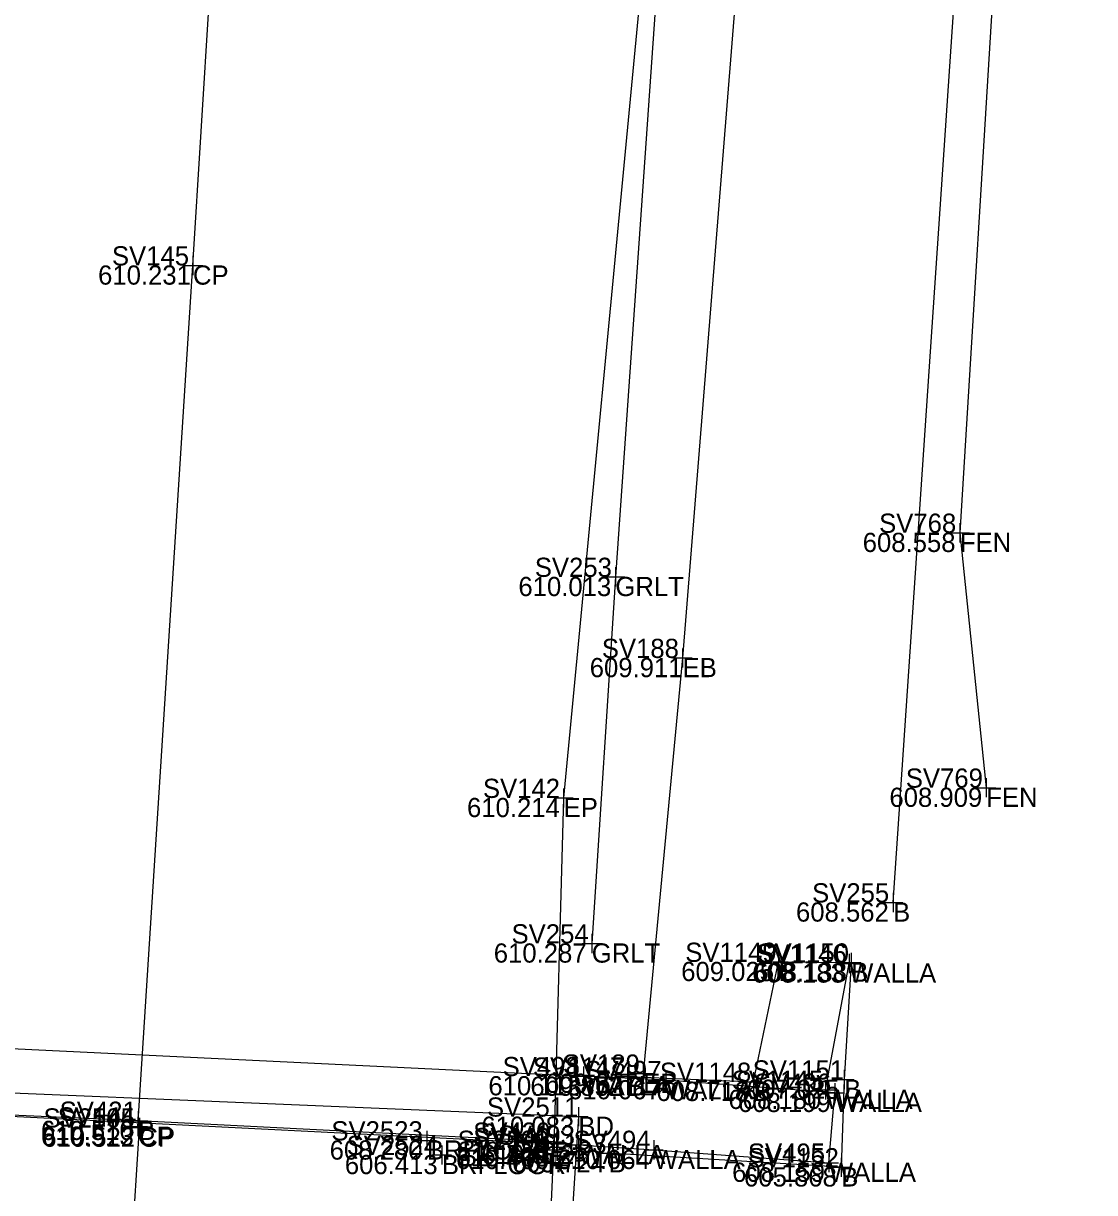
# Model space of a CAD drawing. Extents: x -2 to 1979875, y -2 to 232027.
# Drawn here: x 1978773.9 to 1978801.79, y 231291.3 to 231321.76 of the extents above; entities that cross this region are included whole.
import ezdxf

# ---------------------------------------------------------------- set-up
doc = ezdxf.new("R2010")
doc.units = 0
for name, color, linetype in [('_CIVIL_CONSTRUCTION', 7, 'Continuous'), ('BR_X_SV_Abut', 7, 'Continuous'), ('BR_X_SV_Deck_Floor_Text', 7, 'Continuous'), ('BR_X_SV_Deck_Top', 7, 'Continuous'), ('BR_X_SV_Deck_Top_Text', 7, 'Continuous'), ('GE_P_Alignment', 7, 'Continuous'), ('GE_P_Alignment_100_Curve_Data', 7, 'Continuous'), ('GE_P_Alignment_500_Stations', 7, 'Continuous'), ('GE_X_Alignment', 7, 'Continuous'), ('GE_X_Alignment_1000_Curve_Data', 7, 'Continuous'), ('GE_X_Alignment_1000_Stations', 7, 'Continuous'), ('GE_X_Alignment_100_Curve_Data', 7, 'Continuous'), ('GE_X_Alignment_100_Stations', 7, 'Continuous'), ('RD_X_Fence', 7, 'Continuous'), ('SC_Scratch1', 7, 'Continuous')]:
    doc.layers.add(name, color=color, linetype=linetype)

msp = doc.modelspace()

# ---------------------------------------------------------------- linework, layer by layer
at = {"layer": 'BR_X_SV_Abut'}
for p, q in [((1978764.58, 231295.485), (1978788.479, 231294.331)), ((1978764.125, 231293.766), (1978788.351, 231292.541))]:
    msp.add_line(p, q, dxfattribs=at)
for points in [[(1978794.786, 231293.976), (1978795.398, 231297.268)], [(1978788.351, 231292.541), (1978790.31, 231292.41), (1978794.873, 231292.077), (1978795.027, 231293.897), (1978790.63, 231294.228), (1978788.479, 231294.331)]]:
    msp.add_lwpolyline(points, dxfattribs=at)
at = {"layer": 'BR_X_SV_Deck_Top'}
msp.add_lwpolyline([(1978761.339, 231252.043), (1978764.257, 231294.289), (1978788.348, 231293.277), (1978785.624, 231251.227)], close=True, dxfattribs=at)
at = {"layer": 'GE_P_Alignment'}
for points in [[(1978796.543, 231298.857), (1978798.274, 231324.443), (1978800.704, 231350.055), (1978802.691, 231376.873), (1978804.911, 231401.653), (1978806.885, 231425.398), (1978807.692, 231450.453), (1978809.926, 231474.524), (1978811.781, 231491.704), (1978814.624, 231521.225), (1978818.445, 231546.214), (1978822.849, 231572.066), (1978827.059, 231594.68), (1978834.582, 231618.811), (1978841.486, 231643.192), (1978848.448, 231666.52), (1978859.661, 231691.186), (1978869.566, 231712.589), (1978880.404, 231735.407), (1978890.398, 231756.483), (1978895.241, 231765.92)], [(1978789.627, 231294.318), (1978792.909, 231294.183), (1978793.561, 231297.308), (1978795.454, 231297.29), (1978795.267, 231294.242), (1978795.191, 231291.956), (1978789.137, 231292.325)], [(1978787.716, 231292.624), (1978776.886, 231293.168), (1978764.446, 231293.727)]]:
    msp.add_lwpolyline(points, dxfattribs=at)
at = {"layer": 'GE_P_Alignment_100_Curve_Data'}
msp.add_lwpolyline([(1978801.365, 231447.686), (1978797.734, 231425.84), (1978795.609, 231402.949), (1978794.056, 231378.448), (1978792.74, 231353.579), (1978790.842, 231329.19), (1978789.312, 231307.337), (1978788.697, 231297.789)], dxfattribs=at)
at = {"layer": 'GE_X_Alignment_1000_Curve_Data'}
for points in [[(1978776.88, 231293.019), (1978778.313, 231315.451), (1978779.686, 231337.763), (1978781.119, 231360.475), (1978782.569, 231384.073), (1978784.079, 231408.548), (1978785.737, 231433.04), (1978787.352, 231456.369), (1978789.204, 231480.117), (1978791.477, 231503.648), (1978794.349, 231526.784), (1978797.796, 231550.891), (1978801.515, 231572.898), (1978806.442, 231596.208), (1978812.098, 231619.057), (1978818.629, 231640.775), (1978826, 231662.112), (1978835.057, 231685.412), (1978844.843, 231707.874), (1978854.489, 231728.841), (1978864.575, 231749.812), (1978877.222, 231774.568)], [(1978774.433, 231252.669), (1978775.92, 231277.185), (1978776.918, 231292.992)]]:
    msp.add_lwpolyline(points, dxfattribs=at)
at = {"layer": 'GE_X_Alignment_1000_Stations'}
for points in [[(1978887.054, 231769.497), (1978875.688, 231747.111), (1978865.322, 231725.635), (1978856.257, 231705.079), (1978847.493, 231684.376), (1978839.463, 231663.377), (1978831.793, 231640.155), (1978824.647, 231616.117), (1978817.773, 231591.521), (1978812.873, 231567.295), (1978809.011, 231544.227), (1978805.416, 231519.882), (1978802.367, 231496.191), (1978799.68, 231465.625), (1978797.956, 231442.353), (1978795.891, 231416.691), (1978793.937, 231391.428), (1978792.627, 231370.424), (1978791.336, 231345.811), (1978789.97, 231322.684), (1978787.965, 231301.579), (1978787.711, 231292.48)], [(1978787.697, 231292.411), (1978786.77, 231271.728), (1978785.515, 231252.063)]]:
    msp.add_lwpolyline(points, dxfattribs=at)
at = {"layer": 'GE_X_Alignment_100_Curve_Data'}
for p, q in [((1978778.313, 231315.701), (1978778.313, 231315.201)), ((1978778.063, 231315.451), (1978778.563, 231315.451)), ((1978778.313, 231315.451), (1978778.313, 231315.451)), ((1978798.282, 231308.736), (1978798.282, 231308.236)), ((1978798.032, 231308.486), (1978798.532, 231308.486)), ((1978798.282, 231308.486), (1978798.282, 231308.486)), ((1978789.062, 231307.337), (1978789.562, 231307.337)), ((1978789.312, 231307.587), (1978789.312, 231307.087)), ((1978789.312, 231307.337), (1978789.312, 231307.337)), ((1978790.812, 231305.225), (1978791.312, 231305.225)), ((1978791.062, 231305.475), (1978791.062, 231304.975)), ((1978791.062, 231305.225), (1978791.062, 231305.225)), ((1978787.965, 231301.829), (1978787.965, 231301.329)), ((1978798.718, 231301.846), (1978799.218, 231301.846)), ((1978798.968, 231302.096), (1978798.968, 231301.596)), ((1978798.968, 231301.846), (1978798.968, 231301.846)), ((1978787.715, 231301.579), (1978788.215, 231301.579)), ((1978787.965, 231301.579), (1978787.965, 231301.579)), ((1978796.543, 231299.107), (1978796.543, 231298.607)), ((1978796.293, 231298.857), (1978796.793, 231298.857)), ((1978796.543, 231298.857), (1978796.543, 231298.857)), ((1978788.697, 231298.039), (1978788.697, 231297.539)), ((1978788.447, 231297.789), (1978788.947, 231297.789)), ((1978788.697, 231297.789), (1978788.697, 231297.789)), ((1978793.311, 231297.308), (1978793.811, 231297.308)), ((1978793.561, 231297.558), (1978793.561, 231297.058)), ((1978793.561, 231297.308), (1978793.561, 231297.308)), ((1978795.148, 231297.268), (1978795.648, 231297.268)), ((1978795.204, 231297.29), (1978795.704, 231297.29)), ((1978795.398, 231297.518), (1978795.398, 231297.018)), ((1978795.398, 231297.268), (1978795.398, 231297.268)), ((1978795.454, 231297.54), (1978795.454, 231297.04)), ((1978795.454, 231297.29), (1978795.454, 231297.29)), ((1978788.479, 231294.581), (1978788.479, 231294.081)), ((1978789.627, 231294.568), (1978789.627, 231294.068)), ((1978790.036, 231294.646), (1978790.036, 231294.146)), ((1978788.229, 231294.331), (1978788.729, 231294.331)), ((1978788.479, 231294.331), (1978788.479, 231294.331)), ((1978789.377, 231294.318), (1978789.877, 231294.318)), ((1978789.627, 231294.318), (1978789.627, 231294.318)), ((1978789.786, 231294.396), (1978790.286, 231294.396)), ((1978790.036, 231294.396), (1978790.036, 231294.396)), ((1978790.38, 231294.228), (1978790.88, 231294.228)), ((1978790.63, 231294.478), (1978790.63, 231293.978)), ((1978790.63, 231294.228), (1978790.63, 231294.228)), ((1978792.909, 231294.433), (1978792.909, 231293.933)), ((1978794.786, 231294.226), (1978794.786, 231293.726)), ((1978795.017, 231294.242), (1978795.517, 231294.242)), ((1978795.267, 231294.492), (1978795.267, 231293.992)), ((1978795.267, 231294.242), (1978795.267, 231294.242)), ((1978792.659, 231294.183), (1978793.159, 231294.183)), ((1978792.909, 231294.183), (1978792.909, 231294.183)), ((1978794.536, 231293.976), (1978795.036, 231293.976)), ((1978794.786, 231293.976), (1978794.786, 231293.976)), ((1978795.027, 231294.147), (1978795.027, 231293.647)), ((1978794.777, 231293.897), (1978795.277, 231293.897)), ((1978795.027, 231293.897), (1978795.027, 231293.897)), ((1978776.886, 231293.418), (1978776.886, 231292.918)), ((1978788.348, 231293.527), (1978788.348, 231293.027)), ((1978776.63, 231293.019), (1978777.13, 231293.019)), ((1978776.636, 231293.168), (1978777.136, 231293.168)), ((1978776.88, 231293.269), (1978776.88, 231292.769)), ((1978776.88, 231293.019), (1978776.88, 231293.019)), ((1978776.886, 231293.168), (1978776.886, 231293.168)), ((1978776.918, 231293.242), (1978776.918, 231292.742)), ((1978788.098, 231293.277), (1978788.598, 231293.277)), ((1978788.348, 231293.277), (1978788.348, 231293.277)), ((1978776.668, 231292.992), (1978777.168, 231292.992)), ((1978776.918, 231292.992), (1978776.918, 231292.992)), ((1978784.403, 231292.907), (1978784.403, 231292.407)), ((1978787.711, 231292.73), (1978787.711, 231292.23)), ((1978787.716, 231292.874), (1978787.716, 231292.374)), ((1978788.351, 231292.791), (1978788.351, 231292.291)), ((1978784.153, 231292.657), (1978784.653, 231292.657)), ((1978784.403, 231292.657), (1978784.403, 231292.657)), ((1978784.793, 231292.528), (1978784.793, 231292.028)), ((1978787.447, 231292.411), (1978787.947, 231292.411)), ((1978787.461, 231292.48), (1978787.961, 231292.48)), ((1978787.466, 231292.624), (1978787.966, 231292.624)), ((1978787.697, 231292.661), (1978787.697, 231292.161)), ((1978787.697, 231292.411), (1978787.697, 231292.411)), ((1978787.711, 231292.48), (1978787.711, 231292.48)), ((1978787.716, 231292.624), (1978787.716, 231292.624)), ((1978788.101, 231292.541), (1978788.601, 231292.541)), ((1978788.351, 231292.541), (1978788.351, 231292.541)), ((1978789.137, 231292.575), (1978789.137, 231292.075)), ((1978790.06, 231292.41), (1978790.56, 231292.41)), ((1978790.31, 231292.66), (1978790.31, 231292.16)), ((1978790.31, 231292.41), (1978790.31, 231292.41)), ((1978784.543, 231292.278), (1978785.043, 231292.278)), ((1978784.793, 231292.278), (1978784.793, 231292.278)), ((1978788.887, 231292.325), (1978789.387, 231292.325)), ((1978789.137, 231292.325), (1978789.137, 231292.325)), ((1978794.873, 231292.327), (1978794.873, 231291.827)), ((1978795.191, 231292.206), (1978795.191, 231291.706)), ((1978794.623, 231292.077), (1978795.123, 231292.077)), ((1978794.873, 231292.077), (1978794.873, 231292.077)), ((1978794.941, 231291.956), (1978795.441, 231291.956)), ((1978795.191, 231291.956), (1978795.191, 231291.956))]:
    msp.add_line(p, q, dxfattribs=at)
at = {"layer": 'RD_X_Fence'}
msp.add_lwpolyline([(1978800.45, 231340.668), (1978799.207, 231323.671), (1978798.282, 231308.486), (1978798.968, 231301.846)], dxfattribs=at)
at = {"layer": 'SC_Scratch1'}
msp.add_lwpolyline([(1978888.808, 231768.485), (1978877.882, 231747.21), (1978866.825, 231724.389), (1978857.223, 231702.339), (1978848.244, 231681.507), (1978839.526, 231658.205), (1978831.772, 231633.737), (1978825.103, 231611.479), (1978819.562, 231589.918), (1978815.237, 231567.914), (1978810.741, 231543.659), (1978807.235, 231520.012), (1978805.099, 231498.598), (1978802.191, 231475.113), (1978800.521, 231451.185), (1978799.203, 231426.897), (1978797.071, 231402.161), (1978795.912, 231377.319), (1978794.635, 231352.241), (1978792.961, 231328.96), (1978791.062, 231305.225), (1978790.036, 231294.396)], dxfattribs=at)

# ---------------------------------------------------------------- texts
at = {"layer": '_CIVIL_CONSTRUCTION'}
for s, p in [('610.231', (1978775.843, 231314.951)), ('608.558', (1978795.752, 231307.986)), ('610.013', (1978786.787, 231306.837)), ('609.911', (1978788.644, 231304.725)), ('608.909', (1978796.447, 231301.346)), ('610.214', (1978785.449, 231301.079)), ('608.562', (1978794.015, 231298.357)), ('610.287', (1978786.146, 231297.289)), ('609.025', (1978791.026, 231296.808)), ('608.138', (1978792.924, 231296.79)), ('609.852', (1978787.099, 231293.818)), ('609.877', (1978787.485, 231293.896)), ('607.025', (1978792.732, 231293.742)), ('608.718', (1978790.379, 231293.683)), ('610.510', (1978774.356, 231292.668)), ('610.513', (1978774.355, 231292.519)), ('610.522', (1978774.39, 231292.492)), ('610.466', (1978785.165, 231291.911)), ('610.438', (1978785.181, 231291.98)), ('610.456', (1978785.184, 231292.124)), ('605.724', (1978786.621, 231291.825)), ('605.724', (1978786.621, 231291.825)), ('605.868', (1978792.661, 231291.456))]:
    msp.add_text(s, height=0.5, dxfattribs=at).set_placement(p)
at = {"layer": 'BR_X_SV_Deck_Floor_Text'}
for s, p in [('SV2523', (1978781.917, 231292.657)), ('SV2524', (1978782.316, 231292.278)), ('608.280', (1978781.873, 231292.157)), ('BRFLOOR', (1978784.403, 231292.157)), ('606.413', (1978782.268, 231291.778)), ('BRFLOOR', (1978784.793, 231291.778))]:
    msp.add_text(s, height=0.5, dxfattribs=at).set_placement(p)
at = {"layer": 'BR_X_SV_Deck_Top_Text'}
for s, p in [('SV2511', (1978785.968, 231293.277)), ('610.083', (1978785.823, 231292.777)), ('BD', (1978788.348, 231292.777))]:
    msp.add_text(s, height=0.5, dxfattribs=at).set_placement(p)
at = {"layer": 'GE_P_Alignment_500_Stations'}
for s, p in [('SV1146', (1978792.956, 231297.268)), ('608.183', (1978792.873, 231296.768)), ('WALLA', (1978795.398, 231296.768)), ('SV498', (1978786.376, 231294.331)), ('SV497', (1978788.505, 231294.228)), ('610.113', (1978786.006, 231293.831)), ('610.067', (1978788.079, 231293.728)), ('WALLA', (1978788.479, 231293.831)), ('WALLA', (1978790.63, 231293.728)), ('SV1145', (1978792.341, 231293.976)), ('SV496', (1978792.922, 231293.897)), ('608.180', (1978792.256, 231293.476)), ('WALLA', (1978794.786, 231293.476)), ('608.199', (1978792.506, 231293.397)), ('WALLA', (1978795.027, 231293.397)), ('SV493', (1978786.253, 231292.541)), ('SV494', (1978788.221, 231292.41)), ('610.012', (1978785.823, 231292.041)), ('610.064', (1978787.794, 231291.91)), ('WALLA', (1978788.351, 231292.041)), ('WALLA', (1978790.31, 231291.91)), ('SV495', (1978792.764, 231292.077)), ('608.159', (1978792.352, 231291.577)), ('WALLA', (1978794.873, 231291.577))]:
    msp.add_text(s, height=0.5, dxfattribs=at).set_placement(p)
at = {"layer": 'GE_X_Alignment'}
for s, p in [('SV145', (1978776.204, 231315.451)), ('SV768', (1978796.179, 231308.486)), ('SV253', (1978787.214, 231307.337)), ('SV188', (1978788.959, 231305.225)), ('SV769', (1978796.874, 231301.846)), ('SV142', (1978785.864, 231301.579)), ('SV255', (1978794.434, 231298.857)), ('SV254', (1978786.608, 231297.789)), ('SV1149', (1978791.131, 231297.308)), ('SV1150', (1978793.014, 231297.29)), ('SV1147', (1978787.166, 231294.318)), ('SV189', (1978787.942, 231294.396)), ('SV1148', (1978790.47, 231294.183)), ('SV1151', (1978792.887, 231294.242)), ('SV421', (1978774.843, 231293.168)), ('SV2505', (1978774.421, 231292.992)), ('SV144', (1978774.791, 231293.019)), ('SV420', (1978785.612, 231292.624)), ('SV2500', (1978785.205, 231292.411)), ('SV143', (1978785.613, 231292.48)), ('SV1153', (1978786.703, 231292.325)), ('SV1153', (1978786.703, 231292.325)), ('SV1152', (1978792.753, 231291.956))]:
    msp.add_text(s, height=0.5, dxfattribs=at).set_placement(p)
at = {"layer": 'GE_X_Alignment_100_Stations'}
for s, p in [('CP', (1978778.313, 231314.951)), ('FEN', (1978798.282, 231307.986)), ('GRLT', (1978789.312, 231306.837)), ('EB', (1978791.062, 231304.725)), ('FEN', (1978798.968, 231301.346)), ('EP', (1978787.965, 231301.079)), ('B', (1978796.543, 231298.357)), ('GRLT', (1978788.697, 231297.289)), ('B', (1978793.561, 231296.808)), ('B', (1978795.454, 231296.79)), ('B', (1978789.627, 231293.818)), ('EB', (1978790.036, 231293.896)), ('B', (1978795.267, 231293.742)), ('B', (1978792.909, 231293.683)), ('CP', (1978776.88, 231292.519)), ('B', (1978776.886, 231292.668)), ('CP', (1978776.918, 231292.492)), ('EP', (1978787.697, 231291.911)), ('EP', (1978787.711, 231291.98)), ('B', (1978787.716, 231292.124)), ('B', (1978789.137, 231291.825)), ('B', (1978789.137, 231291.825)), ('B', (1978795.191, 231291.456))]:
    msp.add_text(s, height=0.5, dxfattribs=at).set_placement(p)

doc.saveas('drawing.dxf')
